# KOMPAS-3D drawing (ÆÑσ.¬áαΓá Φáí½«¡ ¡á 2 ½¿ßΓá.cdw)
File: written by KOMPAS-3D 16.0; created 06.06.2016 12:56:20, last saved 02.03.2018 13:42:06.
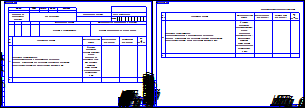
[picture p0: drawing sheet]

Sheets 1-2: A1, landscape

Title block, sheet 1: name: Технологическая / карта; designation: ДП 018.00.00 4ТЧ; scale: 1:1; sheet number: 1; sheets: 2; organisation: САТК - 47; sheet format: A1; revision letter: Д; stored path: C:\Documents and Settings\Admin\Мои документы\Мои рисунки\Базылев опер ката.cdw; drawn by: Ковалёв Р.С.; checked by: Ершов М.В.; standards control: Бервинова Н.К.; approved by: Ященко М.К.
Title block, sheet 2: sheet number: 2; stored path: D:\Методические указания дипломному проекту по зоне ТР АТП\Тех.карта шаблон 1 лист.cdw

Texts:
  Базылев опер карта
  satk
  Normal
  heading 1
Dimensions and other numbers on the sheet: 1:1; 1; 2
